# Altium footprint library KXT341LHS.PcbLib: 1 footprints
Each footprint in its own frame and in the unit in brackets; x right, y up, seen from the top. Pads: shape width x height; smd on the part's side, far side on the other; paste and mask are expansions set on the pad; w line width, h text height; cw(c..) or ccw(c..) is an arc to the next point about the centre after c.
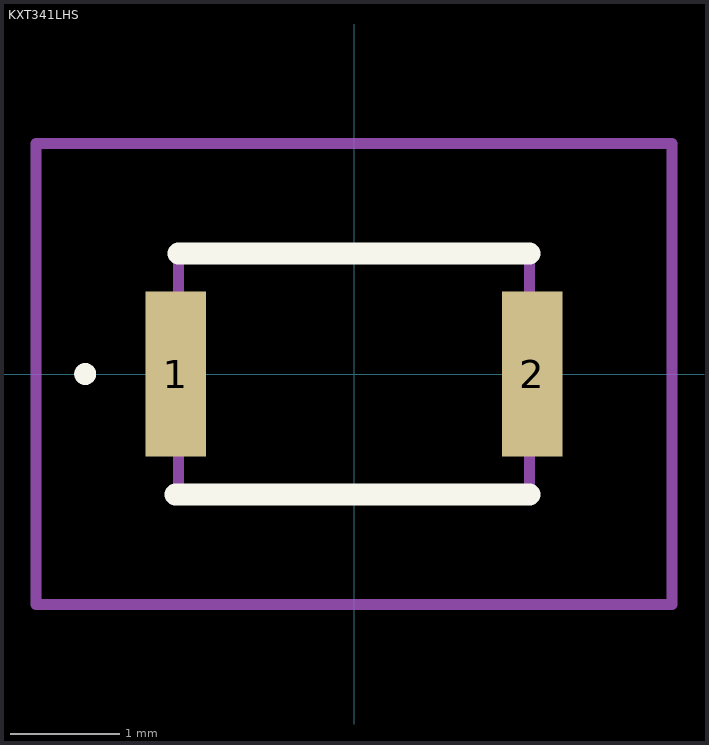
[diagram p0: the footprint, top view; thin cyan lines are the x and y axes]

## KXT341LHS [mm]
pads (2):
  rect 0.55x1.5 smd: 1(-1.625,0) 2(1.625,0)
Top Overlay:
  lines w0.1: -2.5,0 cw(c-2.45,0) -2.4,0 ; -2.5,0 -2.5,0 ; -2.5,0 ccw(c-2.45,0) -2.4,0 ; -2.4,0 -2.4,0
  lines w0.2: -1.625,-1.1 1.6,-1.1 ; -1.6,1.1 1.6,1.1
Mechanical 15:
  lines w0.1: -1.6,-1.1 1.6,-1.1 1.6,1.1 -1.6,1.1 -1.6,-1.1
Mechanical 20:
  lines w0.1: -2.9,-2.1 2.9,-2.1 2.9,2.1 -2.9,2.1 -2.9,-2.1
